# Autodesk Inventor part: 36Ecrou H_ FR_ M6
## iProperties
Created: 2011-01
Part Number: 36Ecrou H_ FR_ M6
Document SubType Name: Modeling
Designer: eric
Density: 1 g/cm^3
Mass: 0.384243 g
Surface Area: 4.02228 cm^2
Volume: 0.384243 cm^3
Author: eric
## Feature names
1. Base1
